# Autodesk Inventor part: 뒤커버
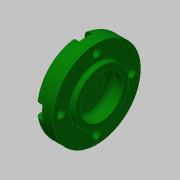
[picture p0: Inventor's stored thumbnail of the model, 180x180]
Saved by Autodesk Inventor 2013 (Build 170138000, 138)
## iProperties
Created: 2015-11
Part Number: 뒤커버
Material: 알루미늄 6061
Document SubType Name: Modeling
Designer: mduedu
Density: 1 g/cm^3
Author: mduedu
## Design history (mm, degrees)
sketch "스케치1"
  geometry: L1 (-7, 0)-(7, 0); L2 (-7, 0)-(-7, 26); L3 (-7, 26)-(4, 26); L4 (4, 26)-(4, 16); L5 (4, 16)-(7, 16); L6 (7, 16)-(7, 0); 2 further points
  constraints: 12 end point, 3 perpendicular, 2 parallel, 1 coincident, 1 horizontal, 1 midpoint
  dimensions: "d0" = 14 distance of L1.start L1.end; "d1" = 52 diameter of L3 L1; "d2" = 3 distance of L4.end L5.end; "d3" = 32 diameter of L5 L1
revolve "회전1" sketch "스케치1" stored, may be unused: angle "d4" = 90 deg
hole "구멍1" diameter "d7" = 25; stored, may be unused: countersink angle "d11" = 90 deg, drill point angle "d13" = 0 deg; dims "d8" = 6, "d9" = 4, "d10" = 2, "d12" = 8, "d62" = 10, "d63" = 10
fillet "모깎기2" dims "d36" = 3
fillet "모깎기3" dims "d37" = 3
fillet "모깎기4" dims "d38" = 0.3
sketch "스케치3" dims "d61" = 42
  geometry: C1 r 26 at (0, 0) reference; 2 further points
  constraints: 2 vertical alignment, 1 coincident, 2 other
hole "구멍4" sketch "스케치3" at (0, -21) diameter "d44" = 4.5; stored, may be unused: countersink angle "d48" = 90 deg, drill point angle "d50" = 0 deg; dims "d45" = 6, "d46" = 8, "d47" = 4.6, "d49" = 8
sketch "스케치4"
  geometry: L1 (-4, 0)-(-4, -4.69); L2 (4, 0)-(4, -4.69); A1 r 4 centre (0, 0) between (3.614, -1.714) and (-3.614, -1.714) reference; A2 r 26 centre (0, 21) between (-4, -4.69) and (4, -4.69) reference; 1 further point
  constraints: 4 end point, 4 point on circle, 2 tangent, 1 parallel, 1 vertical
extrude "돌출1" cut sketch "스케치4" stored distance "d51" = 0; taper "d52" = 0 deg
node "솔리드1"
pattern_circular "원형 패턴1" dims angle "d54" = 360 deg
